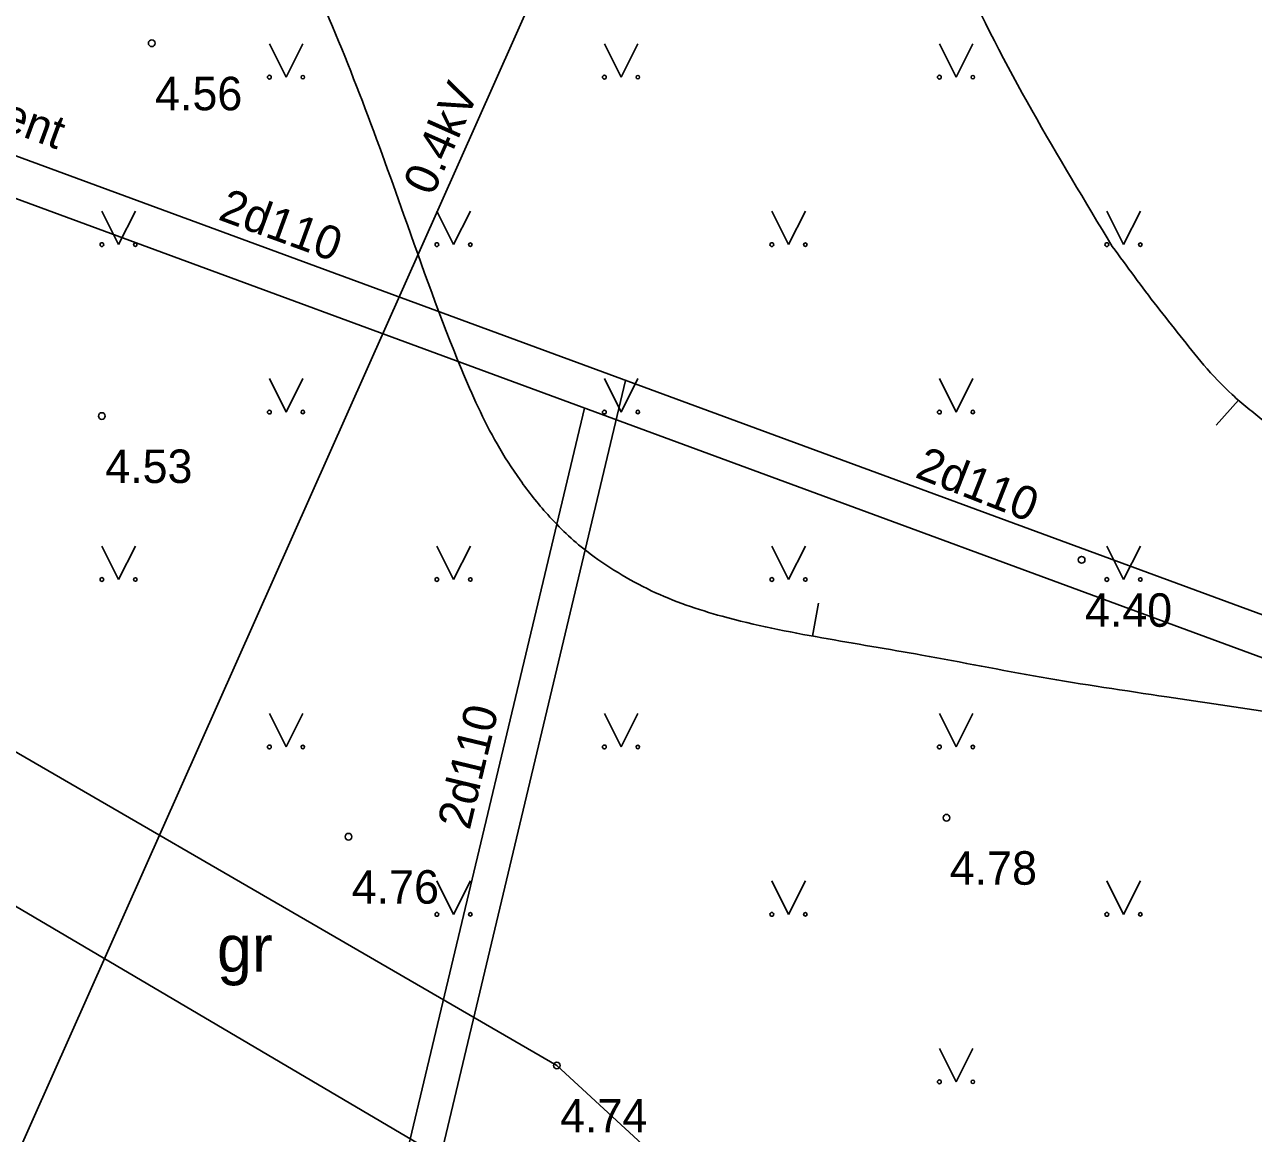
# Model space of a CAD drawing. Extents: x 519536 to 519949, y 326041 to 326519.
# Drawn here: x 519691.1 to 519709.44, y 326174.23 to 326190.79 of the extents above; entities that cross this region are included whole.
import ezdxf

# ---------------------------------------------------------------- set-up
doc = ezdxf.new("R2010")
doc.units = 0
for name, color, linetype in [('CELI_CMAL_####_####_#', 7, 'Continuous'), ('CELI_CSEG_####_TKST_#', 7, 'Continuous'), ('ELEK_VADV_ZSPR_####_#', 7, 'Continuous'), ('ELEK_VADV_ZSPR_TKST_#', 7, 'Continuous'), ('RELJ_AATZ_####_TKST_#', 7, 'Continuous'), ('RELJ_ELEM_####_####_#', 7, 'Continuous'), ('RELJ_HORZ_PAMT_####_#', 7, 'Continuous'), ('SILT_VADP_UDEN_####_#', 7, 'Continuous'), ('SILT_VADP_UDEN_TKST_#', 7, 'Continuous'), ('TERT_ELEM_####_####_#', 7, 'Continuous')]:
    doc.layers.add(name, color=color, linetype=linetype)

msp = doc.modelspace()

# ---------------------------------------------------------------- linework, layer by layer
at = {"layer": 'CELI_CMAL_####_####_#'}
for points in [[(519725.6, 326145.595), (519722.795, 326148.479), (519717.487, 326152.615), (519712.383, 326157.466), (519706.872, 326166.697), (519703.889, 326170.776), (519699.04, 326175.245), (519687.684, 326181.825), (519678.238, 326187.413), (519670.804, 326192.027), (519670.048, 326192.682), (519664.865, 326189.411), (519662.65, 326188.197)], [(519662.737, 326185.995), (519665.714, 326187.6), (519670.496, 326188.216), (519674.588, 326187.052), (519687.563, 326179.623), (519697.361, 326173.852), (519702.298, 326169.28), (519707.151, 326162.302), (519711.634, 326155.197), (519719.91, 326147.956), (519722.688, 326145.028)]]:
    msp.add_lwpolyline(points, dxfattribs=at)
at = {"layer": 'ELEK_VADV_ZSPR_####_#'}
msp.add_line((519666.72, 326119.401), (519722.531, 326244.78), dxfattribs=at)
at = {"layer": 'RELJ_ELEM_####_####_#'}
for centre in [(519692.994, 326190.506), (519692.25, 326184.941), (519706.874, 326182.794), (519704.856, 326178.943), (519695.93, 326178.66), (519699.04, 326175.245)]:
    msp.add_circle(centre, 0.05, dxfattribs=at)
at = {"layer": 'RELJ_HORZ_PAMT_####_#'}
for p, q in [((519709.213, 326185.179), (519708.884, 326184.803)), ((519702.948, 326182.147), (519702.857, 326181.655))]:
    msp.add_line(p, q, dxfattribs=at)
for points in [[(519679.571, 326197.325), (519680.165, 326196.852), (519680.813, 326196.657), (519682.865, 326196.481), (519684.919, 326196.331), (519689.028, 326196.07), (519690.241, 326196.004), (519691.17, 326195.809), (519691.617, 326195.63), (519692.053, 326195.411), (519692.478, 326195.145), (519692.871, 326194.841), (519693.625, 326194.147), (519694.626, 326192.899), (519695.352, 326191.531), (519696.758, 326187.942), (519697.617, 326185.639), (519698.149, 326184.524), (519698.492, 326183.987), (519698.688, 326183.726), (519698.904, 326183.469), (519699.481, 326182.926), (519699.954, 326182.603), (519700.45, 326182.333), (519701.508, 326181.951), (519702.995, 326181.63), (519704.488, 326181.372), (519706.268, 326181.042), (519708.146, 326180.748), (519709.744, 326180.513), (519711.344, 326180.291), (519712.944, 326180.068), (519714.544, 326179.832), (519716.461, 326179.296), (519716.985, 326179.075)], [(519707.332, 326187.473), (519705.06, 326191.602), (519704.947, 326191.858)], [(519721.523, 326176.975), (519722.809, 326176.363), (519724.924, 326175.383), (519725.012, 326175.345), (519725.337, 326175.344), (519726.068, 326175.653), (519726.758, 326176.037), (519728.015, 326177.021), (519729.101, 326178.213), (519730.066, 326179.615), (519730.72, 326181.206), (519730.783, 326181.593), (519730.787, 326181.995), (519730.76, 326182.191), (519730.719, 326182.385), (519730.578, 326182.753), (519728.543, 326186.427), (519728.385, 326186.716), (519728.18, 326187.143), (519728.082, 326187.36), (519727.979, 326187.574), (519727.633, 326188.127), (519727.398, 326188.394), (519727.105, 326188.653), (519726.598, 326188.831), (519726.09, 326188.807), (519725.422, 326188.707), (519724.754, 326188.519), (519724.086, 326188.373), (519723.418, 326188.397), (519723.067, 326188.494), (519722.723, 326188.607), (519722.385, 326188.735), (519722.051, 326188.879), (519721.396, 326189.182), (519720.755, 326189.51), (519720.519, 326189.65), (519720.292, 326189.807), (519720.061, 326189.958), (519719.94, 326190.023), (519719.813, 326190.074), (519719.716, 326190.08), (519719.617, 326190.061), (519719.419, 326190.014), (519719.214, 326189.936), (519719.017, 326189.842), (519718.214, 326189.385), (519716.631, 326188.539), (519715.863, 326188.085), (519715.493, 326187.833), (519715.133, 326187.56), (519714.124, 326186.531), (519713.305, 326185.337), (519713.164, 326185.067), (519713.058, 326184.765), (519712.948, 326184.477), (519712.795, 326184.245), (519712.396, 326184.001), (519711.989, 326183.948), (519711.568, 326183.971), (519710.749, 326184.208), (519709.596, 326184.868), (519709.353, 326185.06), (519709.12, 326185.261), (519708.698, 326185.702), (519708.345, 326186.138), (519707.999, 326186.577), (519707.332, 326187.473)]]:
    msp.add_spline(points, degree=3, dxfattribs=at)
at = {"layer": 'SILT_VADP_UDEN_####_#'}
for p, q in [((519729.114, 326174.771), (519670.3, 326196.44)), ((519728.534, 326174.345), (519670.092, 326195.877)), ((519696.701, 326171.354), (519700.067, 326185.473)), ((519696.333, 326171.964), (519699.455, 326185.059))]:
    msp.add_line(p, q, dxfattribs=at)
at = {"layer": 'TERT_ELEM_####_####_#'}
for p, q in [((519694.75, 326190.5), (519695, 326190)), ((519695, 326190), (519695.25, 326190.5)), ((519699.75, 326190.5), (519700, 326190)), ((519700, 326190), (519700.25, 326190.5)), ((519704.75, 326190.5), (519705, 326190)), ((519705, 326190), (519705.25, 326190.5)), ((519692.25, 326188), (519692.5, 326187.5)), ((519692.5, 326187.5), (519692.75, 326188)), ((519697.25, 326188), (519697.5, 326187.5)), ((519697.5, 326187.5), (519697.75, 326188)), ((519702.25, 326188), (519702.5, 326187.5)), ((519702.5, 326187.5), (519702.75, 326188)), ((519707.25, 326188), (519707.5, 326187.5)), ((519707.5, 326187.5), (519707.75, 326188)), ((519694.75, 326185.5), (519695, 326185)), ((519695, 326185), (519695.25, 326185.5)), ((519699.75, 326185.5), (519700, 326185)), ((519700, 326185), (519700.25, 326185.5)), ((519704.75, 326185.5), (519705, 326185)), ((519705, 326185), (519705.25, 326185.5)), ((519692.25, 326183), (519692.5, 326182.5)), ((519692.5, 326182.5), (519692.75, 326183)), ((519697.25, 326183), (519697.5, 326182.5)), ((519697.5, 326182.5), (519697.75, 326183)), ((519702.25, 326183), (519702.5, 326182.5)), ((519702.5, 326182.5), (519702.75, 326183)), ((519707.25, 326183), (519707.5, 326182.5)), ((519707.5, 326182.5), (519707.75, 326183)), ((519694.75, 326180.5), (519695, 326180)), ((519695, 326180), (519695.25, 326180.5)), ((519699.75, 326180.5), (519700, 326180)), ((519700, 326180), (519700.25, 326180.5)), ((519704.75, 326180.5), (519705, 326180)), ((519705, 326180), (519705.25, 326180.5)), ((519697.25, 326178), (519697.5, 326177.5)), ((519697.5, 326177.5), (519697.75, 326178)), ((519702.25, 326178), (519702.5, 326177.5)), ((519702.5, 326177.5), (519702.75, 326178)), ((519707.25, 326178), (519707.5, 326177.5)), ((519707.5, 326177.5), (519707.75, 326178)), ((519704.75, 326175.5), (519705, 326175)), ((519705, 326175), (519705.25, 326175.5))]:
    msp.add_line(p, q, dxfattribs=at)
for centre, radius in [((519694.75, 326190), 0.028), ((519695.25, 326190), 0.0263), ((519699.75, 326190), 0.028), ((519700.25, 326190), 0.0263), ((519704.75, 326190), 0.028), ((519705.25, 326190), 0.0263), ((519692.25, 326187.5), 0.028), ((519692.75, 326187.5), 0.0263), ((519697.25, 326187.5), 0.028), ((519697.75, 326187.5), 0.0263), ((519702.25, 326187.5), 0.028), ((519702.75, 326187.5), 0.0263), ((519707.25, 326187.5), 0.028), ((519707.75, 326187.5), 0.0263), ((519694.75, 326185), 0.028), ((519695.25, 326185), 0.0263), ((519699.75, 326185), 0.028), ((519700.25, 326185), 0.0263), ((519704.75, 326185), 0.028), ((519705.25, 326185), 0.0263), ((519692.25, 326182.5), 0.028), ((519692.75, 326182.5), 0.0263), ((519697.25, 326182.5), 0.028), ((519697.75, 326182.5), 0.0263), ((519702.25, 326182.5), 0.028), ((519702.75, 326182.5), 0.0263), ((519707.25, 326182.5), 0.028), ((519707.75, 326182.5), 0.0263), ((519694.75, 326180), 0.028), ((519695.25, 326180), 0.0263), ((519699.75, 326180), 0.028), ((519700.25, 326180), 0.0263), ((519704.75, 326180), 0.028), ((519705.25, 326180), 0.0263), ((519697.25, 326177.5), 0.028), ((519697.75, 326177.5), 0.0263), ((519702.25, 326177.5), 0.028), ((519702.75, 326177.5), 0.0263), ((519707.25, 326177.5), 0.028), ((519707.75, 326177.5), 0.0263), ((519704.75, 326175), 0.028), ((519705.25, 326175), 0.0263)]:
    msp.add_circle(centre, radius, dxfattribs=at)

# ---------------------------------------------------------------- texts
at = {"layer": 'CELI_CSEG_####_TKST_#'}
msp.add_text('gr', height=0.7, dxfattribs=at).set_placement((519693.968, 326176.643))
at = {"layer": 'ELEK_VADV_ZSPR_TKST_#'}
msp.add_text('0.4kV', height=0.5, rotation=66.0045, dxfattribs=at).set_placement((519697.186, 326188.21))
at = {"layer": 'RELJ_AATZ_####_TKST_#'}
for s, p in [('4.56', (519693.044, 326189.506)), ('4.53', (519692.3, 326183.941)), ('4.40', (519706.924, 326181.794)), ('4.78', (519704.906, 326177.943)), ('4.76', (519695.98, 326177.66)), ('4.74', (519699.09, 326174.245))]:
    msp.add_text(s, height=0.5, dxfattribs=at).set_placement(p)
at = {"layer": 'SILT_VADP_UDEN_TKST_#'}
for s, rotation, p in [('orient', 339.7744, (519690.011, 326189.498)), ('2d110', 339.8926, (519693.968, 326187.88)), ('2d110', 338.4892, (519704.369, 326184.033)), ('2d110', 76.4804, (519697.739, 326178.747))]:
    msp.add_text(s, height=0.5, rotation=rotation, dxfattribs=at).set_placement(p)

doc.saveas('drawing.dxf')
